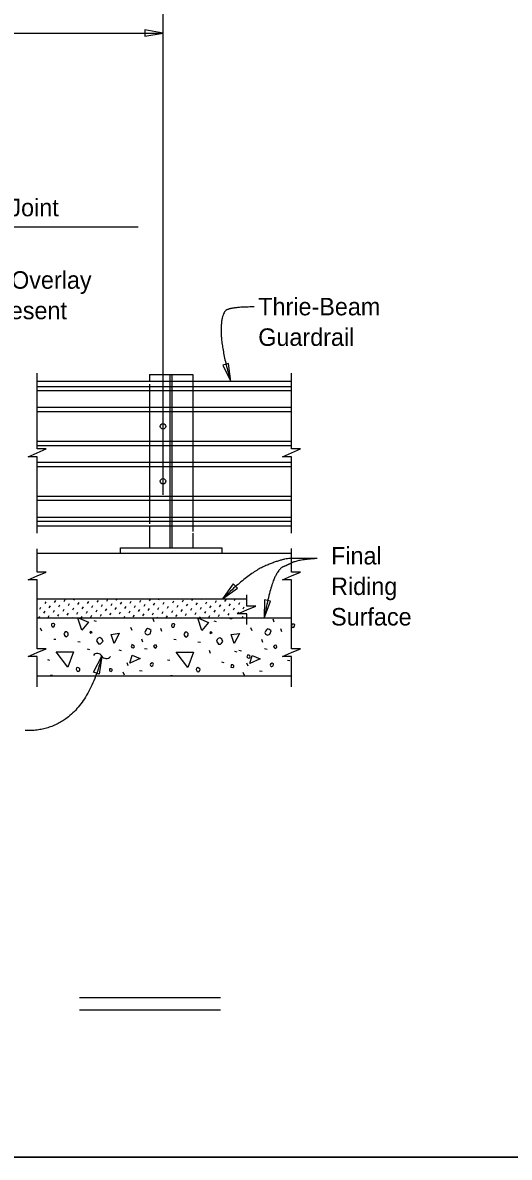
# Model space of a CAD drawing. Extents: x 0 to 41.1, y 0 to 25.9.
# Drawn here: x 15.65 to 21.27, y 0 to 13.09 of the extents above; entities that cross this region are included whole.
import ezdxf

# ---------------------------------------------------------------- set-up
doc = ezdxf.new("R2010")
doc.units = 0
for name, color, linetype in [('Dimension', 7, 'Continuous'), ('ExistSuperStruct', 7, 'Continuous'), ('Miscellaneous', 7, 'Continuous'), ('Miscellaneous1', 7, 'Continuous'), ('SteelMisc', 7, 'Continuous'), ('SteelMisc_h', 7, 'Continuous'), ('TextStructures', 7, 'Continuous')]:
    doc.layers.add(name, color=color, linetype=linetype)

msp = doc.modelspace()

# ---------------------------------------------------------------- linework, layer by layer
at = {"layer": 'Dimension'}
for p, q in [((17.272, 7.641), (17.272, 21.686)), ((16.984, 10.732), (11.432, 10.732)), ((16.308, 1.842), (17.936, 1.842)), ((16.308, 1.7), (17.936, 1.7))]:
    msp.add_line(p, q, dxfattribs=at)
for points in [[(5.085, 12.97), (11.216, 12.97), (11.216, 13.073), (11.261, 12.97), (11.306, 12.866), (11.306, 12.97), (17.272, 12.97)], [(15.819, 7.199), (15.819, 8.082), (15.716, 8.082), (15.819, 8.127), (15.923, 8.172), (15.819, 8.172), (15.819, 9.045)], [(18.755, 7.199), (18.755, 8.082), (18.652, 8.082), (18.755, 8.127), (18.858, 8.172), (18.755, 8.172), (18.755, 9.045)], [(15.819, 6.192), (15.819, 6.662), (15.716, 6.662), (15.819, 6.707), (15.923, 6.752), (15.819, 6.752), (15.819, 7.02)], [(18.755, 6.192), (18.755, 6.662), (18.652, 6.662), (18.755, 6.707), (18.858, 6.752), (18.755, 6.752), (18.755, 7.023)], [(18.241, 6.148), (18.241, 6.269), (18.137, 6.269), (18.241, 6.314), (18.344, 6.359), (18.241, 6.359), (18.241, 6.489)], [(15.819, 5.427), (15.819, 5.777), (15.716, 5.777), (15.819, 5.822), (15.923, 5.867), (15.819, 5.867), (15.819, 6.192)], [(18.755, 5.427), (18.755, 5.777), (18.652, 5.777), (18.755, 5.822), (18.858, 5.867), (18.755, 5.867), (18.755, 6.192)]]:
    msp.add_lwpolyline(points, dxfattribs=at)
for points in [[(17.272, 12.97), (17.064, 13.005), (17.064, 12.934)], [(18.054, 8.948), (18.029, 9.158), (17.961, 9.138)], [(17.96, 6.443), (18.133, 6.565), (18.083, 6.615)], [(18.438, 6.219), (18.512, 6.417), (18.443, 6.43)], [(16.567, 5.783), (16.537, 5.574), (16.47, 5.596)]]:
    msp.add_lwpolyline(points, close=True, dxfattribs=at)
for centre, start, end in [((16.515, 5.753), 30.0081, 141.7354), ((16.618, 5.813), 210.0081, 321.7354)]:
    msp.add_arc(centre, 0.0596, start, end, dxfattribs=at)
for points in [[(18.324, 9.81), (18.084, 9.81), (17.942, 9.746), (17.942, 9.325), (18.054, 8.948)], [(19.049, 6.909), (18.858, 6.909), (18.653, 6.909), (18.257, 6.74), (17.96, 6.443)], [(19.049, 6.909), (18.823, 6.891), (18.699, 6.827), (18.616, 6.797), (18.512, 6.597), (18.438, 6.219)], [(16.567, 5.783), (16.347, 4.909), (15.683, 4.922)]]:
    msp.add_open_spline(points, degree=2, dxfattribs=at)
at = {"layer": 'ExistSuperStruct'}
for p, q in [((15.819, 6.97), (18.755, 6.97)), ((18.241, 6.439), (15.819, 6.439)), ((18.755, 6.22), (15.819, 6.22)), ((15.819, 5.553), (18.755, 5.553))]:
    msp.add_line(p, q, dxfattribs=at)
at = {"layer": 'Miscellaneous'}
for p, q in [((15.862, 6.436), (15.863, 6.439)), ((16.021, 6.4), (16.034, 6.422)), ((16.132, 6.413), (16.145, 6.435)), ((16.243, 6.426), (16.25, 6.439)), ((16.513, 6.403), (16.526, 6.425)), ((16.623, 6.416), (16.636, 6.438)), ((16.734, 6.429), (16.74, 6.439)), ((16.893, 6.393), (16.906, 6.415)), ((17.004, 6.406), (17.017, 6.428)), ((17.115, 6.419), (17.126, 6.439)), ((17.225, 6.432), (17.229, 6.439)), ((17.385, 6.396), (17.398, 6.419)), ((17.495, 6.409), (17.508, 6.431)), ((17.606, 6.422), (17.616, 6.439)), ((17.717, 6.435), (17.719, 6.439)), ((17.876, 6.399), (17.889, 6.422)), ((17.987, 6.412), (18, 6.434)), ((18.097, 6.425), (18.105, 6.439)), ((18.208, 6.438), (18.208, 6.439)), ((15.849, 6.325), (15.862, 6.348)), ((15.898, 6.276), (15.911, 6.299)), ((15.911, 6.387), (15.924, 6.409)), ((15.96, 6.338), (15.973, 6.361)), ((16.008, 6.289), (16.021, 6.312)), ((16.07, 6.351), (16.083, 6.374)), ((16.119, 6.302), (16.132, 6.325)), ((16.181, 6.364), (16.194, 6.387)), ((16.23, 6.315), (16.243, 6.338)), ((16.279, 6.266), (16.291, 6.289)), ((16.291, 6.377), (16.304, 6.4)), ((16.34, 6.328), (16.353, 6.351)), ((16.389, 6.279), (16.402, 6.302)), ((16.402, 6.39), (16.415, 6.412)), ((16.451, 6.341), (16.464, 6.364)), ((16.5, 6.292), (16.513, 6.315)), ((16.562, 6.354), (16.575, 6.377)), ((16.61, 6.305), (16.623, 6.328)), ((16.672, 6.367), (16.685, 6.39)), ((16.721, 6.318), (16.734, 6.341)), ((16.77, 6.27), (16.783, 6.292)), ((16.783, 6.38), (16.796, 6.403)), ((16.832, 6.331), (16.845, 6.354)), ((16.88, 6.282), (16.893, 6.305)), ((16.942, 6.344), (16.955, 6.367)), ((16.991, 6.295), (17.004, 6.318)), ((17.053, 6.357), (17.066, 6.38)), ((17.102, 6.308), (17.115, 6.331)), ((17.164, 6.37), (17.177, 6.393)), ((17.212, 6.321), (17.225, 6.344)), ((17.261, 6.273), (17.274, 6.295)), ((17.274, 6.383), (17.287, 6.406)), ((17.323, 6.334), (17.336, 6.357)), ((17.372, 6.285), (17.385, 6.308)), ((17.434, 6.347), (17.447, 6.37)), ((17.482, 6.298), (17.495, 6.321)), ((17.544, 6.36), (17.557, 6.383)), ((17.593, 6.311), (17.606, 6.334)), ((17.642, 6.263), (17.655, 6.285)), ((17.655, 6.373), (17.668, 6.396)), ((17.704, 6.324), (17.717, 6.347)), ((17.753, 6.276), (17.766, 6.298)), ((17.766, 6.386), (17.779, 6.409)), ((17.814, 6.337), (17.827, 6.36)), ((17.863, 6.289), (17.876, 6.311)), ((17.925, 6.35), (17.938, 6.373)), ((17.974, 6.301), (17.987, 6.324)), ((18.036, 6.363), (18.049, 6.386)), ((18.084, 6.314), (18.097, 6.337)), ((18.133, 6.266), (18.146, 6.288)), ((18.146, 6.376), (18.159, 6.399)), ((18.195, 6.327), (18.208, 6.35)), ((15.839, 6.22), (15.849, 6.237)), ((15.947, 6.228), (15.96, 6.25)), ((16.057, 6.241), (16.07, 6.263)), ((16.168, 6.254), (16.181, 6.276)), ((16.225, 6.22), (16.23, 6.227)), ((16.329, 6.22), (16.34, 6.24)), ((16.438, 6.231), (16.451, 6.253)), ((16.473, 6.193), (16.501, 6.185)), ((16.549, 6.244), (16.562, 6.266)), ((16.659, 6.257), (16.672, 6.279)), ((16.715, 6.22), (16.721, 6.23)), ((16.819, 6.221), (16.832, 6.243)), ((16.929, 6.234), (16.942, 6.256)), ((17.04, 6.247), (17.053, 6.269)), ((17.102, 6.22), (17.102, 6.22)), ((17.151, 6.26), (17.164, 6.282)), ((17.171, 6.177), (17.157, 6.212)), ((17.205, 6.22), (17.212, 6.233)), ((17.31, 6.224), (17.323, 6.246)), ((17.421, 6.237), (17.434, 6.259)), ((17.531, 6.25), (17.544, 6.272)), ((17.591, 6.22), (17.593, 6.223)), ((17.694, 6.22), (17.704, 6.236)), ((17.801, 6.227), (17.814, 6.249)), ((17.858, 6.189), (17.886, 6.182)), ((17.912, 6.24), (17.925, 6.262)), ((18.023, 6.253), (18.036, 6.275)), ((18.081, 6.22), (18.084, 6.226)), ((18.184, 6.22), (18.195, 6.239)), ((18.556, 6.173), (18.542, 6.208)), ((15.874, 6.068), (15.86, 6.103)), ((16.915, 6.076), (16.901, 6.111)), ((17.259, 6.064), (17.245, 6.099)), ((18.3, 6.072), (18.285, 6.108)), ((18.644, 6.061), (18.63, 6.096)), ((16.012, 5.979), (16.037, 5.976)), ((16.288, 5.951), (16.318, 5.946)), ((17.04, 5.943), (17.028, 5.977)), ((17.397, 5.976), (17.422, 5.972)), ((17.673, 5.947), (17.703, 5.942)), ((18.425, 5.94), (18.413, 5.973)), ((16.395, 5.867), (16.423, 5.86)), ((16.763, 5.853), (16.791, 5.846)), ((17.059, 5.871), (17.089, 5.866)), ((17.821, 5.813), (17.809, 5.847)), ((18.095, 5.84), (18.123, 5.833)), ((18.148, 5.85), (18.176, 5.843)), ((18.444, 5.868), (18.474, 5.863)), ((15.938, 5.742), (15.964, 5.737)), ((16.869, 5.671), (16.857, 5.704)), ((17.323, 5.739), (17.349, 5.734)), ((17.948, 5.714), (17.975, 5.709)), ((18.254, 5.667), (18.241, 5.701)), ((18.707, 5.735), (18.734, 5.73)), ((16.827, 5.561), (16.812, 5.596)), ((16.999, 5.617), (17.031, 5.613)), ((18.211, 5.557), (18.197, 5.593)), ((18.384, 5.613), (18.416, 5.61))]:
    msp.add_line(p, q, dxfattribs=at)
for points in [[(15.984, 6.135), (15.993, 6.119), (16.012, 6.121), (16.021, 6.133), (16.023, 6.152), (16.01, 6.158), (16.002, 6.16), (15.991, 6.156), (15.987, 6.152), (15.984, 6.135)], [(16.336, 6.08), (16.29, 6.22)], [(16.304, 6.22), (16.413, 6.172), (16.336, 6.08)], [(17.369, 6.131), (17.377, 6.115), (17.397, 6.117), (17.406, 6.13), (17.407, 6.149), (17.395, 6.154), (17.386, 6.156), (17.376, 6.152), (17.372, 6.149), (17.369, 6.131)], [(17.72, 6.076), (17.674, 6.22)], [(17.681, 6.22), (17.798, 6.168), (17.72, 6.076)], [(18.042, 6.22), (18.045, 6.214), (18.041, 6.217)], [(18.045, 6.214), (18.066, 6.214), (18.072, 6.22)], [(18.753, 6.128), (18.762, 6.112), (18.782, 6.114), (18.79, 6.126), (18.792, 6.145), (18.78, 6.151), (18.771, 6.152), (18.76, 6.149), (18.757, 6.145), (18.753, 6.128)], [(16.129, 6.036), (16.139, 6.015), (16.157, 6.004), (16.171, 6.015), (16.178, 6.025), (16.178, 6.046), (16.162, 6.062), (16.143, 6.061), (16.134, 6.052), (16.129, 6.036)], [(16.435, 6.045), (16.454, 6.054), (16.447, 6.061), (16.435, 6.066), (16.429, 6.054), (16.435, 6.045)], [(16.708, 5.929), (16.674, 6.033), (16.768, 6.046), (16.708, 5.929)], [(17.069, 6.039), (17.092, 6.026), (17.122, 6.039), (17.134, 6.076), (17.116, 6.094), (17.093, 6.099), (17.083, 6.092), (17.07, 6.072), (17.062, 6.056), (17.069, 6.039)], [(17.514, 6.032), (17.524, 6.011), (17.542, 6), (17.556, 6.011), (17.563, 6.022), (17.563, 6.043), (17.547, 6.059), (17.528, 6.057), (17.519, 6.048), (17.514, 6.032)], [(17.819, 6.041), (17.839, 6.05), (17.832, 6.057), (17.819, 6.062), (17.814, 6.05), (17.819, 6.041)], [(18.093, 5.926), (18.059, 6.03), (18.153, 6.042), (18.093, 5.926)], [(18.453, 6.035), (18.476, 6.023), (18.506, 6.035), (18.519, 6.072), (18.501, 6.09), (18.478, 6.095), (18.468, 6.088), (18.455, 6.069), (18.446, 6.053), (18.453, 6.035)], [(16.505, 5.96), (16.528, 5.923), (16.551, 5.924), (16.56, 5.933), (16.58, 5.953), (16.567, 5.983), (16.543, 5.997), (16.525, 5.99), (16.511, 5.976), (16.505, 5.96)], [(16.914, 5.88), (16.926, 5.878), (16.939, 5.884), (16.942, 5.894), (16.937, 5.903), (16.926, 5.91), (16.914, 5.916), (16.907, 5.901), (16.903, 5.891), (16.914, 5.88)], [(17.171, 5.884), (17.181, 5.873), (17.192, 5.88), (17.199, 5.891), (17.195, 5.909), (17.187, 5.91), (17.174, 5.909), (17.164, 5.898), (17.171, 5.884)], [(17.89, 5.956), (17.913, 5.919), (17.936, 5.921), (17.945, 5.93), (17.964, 5.949), (17.952, 5.979), (17.927, 5.993), (17.91, 5.986), (17.895, 5.972), (17.89, 5.956)], [(18.555, 5.88), (18.566, 5.87), (18.577, 5.877), (18.584, 5.887), (18.58, 5.905), (18.571, 5.907), (18.559, 5.905), (18.548, 5.894), (18.555, 5.88)], [(16.173, 5.656), (16.039, 5.833), (16.238, 5.831), (16.173, 5.656)], [(16.888, 5.7), (16.916, 5.792), (17.01, 5.755), (16.888, 5.7)], [(17.558, 5.652), (17.423, 5.829), (17.623, 5.827), (17.558, 5.652)], [(18.25, 5.761), (18.262, 5.759), (18.275, 5.765), (18.278, 5.775), (18.273, 5.784), (18.262, 5.791), (18.25, 5.797), (18.243, 5.782), (18.239, 5.772), (18.25, 5.761)], [(18.272, 5.696), (18.301, 5.788), (18.394, 5.751), (18.272, 5.696)], [(16.272, 5.624), (16.281, 5.608), (16.302, 5.604), (16.311, 5.62), (16.314, 5.635), (16.306, 5.643), (16.29, 5.652), (16.274, 5.647), (16.269, 5.631), (16.272, 5.624)], [(16.653, 5.611), (16.672, 5.606), (16.685, 5.614), (16.687, 5.627), (16.683, 5.63), (16.669, 5.637), (16.656, 5.636), (16.655, 5.623), (16.653, 5.611)], [(17.135, 5.665), (17.142, 5.665), (17.156, 5.672), (17.162, 5.688), (17.16, 5.696), (17.146, 5.703), (17.128, 5.693), (17.125, 5.682), (17.128, 5.672), (17.135, 5.665)], [(17.657, 5.62), (17.666, 5.604), (17.687, 5.601), (17.696, 5.617), (17.699, 5.631), (17.69, 5.64), (17.674, 5.649), (17.659, 5.643), (17.653, 5.627), (17.657, 5.62)], [(18.056, 5.656), (18.076, 5.65), (18.088, 5.659), (18.09, 5.672), (18.086, 5.675), (18.072, 5.682), (18.06, 5.681), (18.058, 5.668), (18.056, 5.656)], [(18.52, 5.661), (18.527, 5.661), (18.541, 5.668), (18.546, 5.684), (18.545, 5.693), (18.531, 5.7), (18.513, 5.689), (18.509, 5.679), (18.513, 5.668), (18.52, 5.661)], [(15.997, 5.553), (15.996, 5.557), (15.973, 5.559), (15.971, 5.553)], [(17.381, 5.553), (17.381, 5.553), (17.358, 5.555), (17.357, 5.553)]]:
    msp.add_lwpolyline(points, dxfattribs=at)
at = {"layer": 'Miscellaneous1'}
msp.add_lwpolyline([(0, 25.946), (41.051, 25.946), (41.051, 0), (0, 0)], close=True, dxfattribs=at)
at = {"layer": 'SteelMisc'}
for p, q in [((17.116, 9.032), (17.616, 9.032)), ((17.116, 9.032), (17.116, 8.949)), ((18.755, 8.949), (15.819, 8.949)), ((15.819, 8.893), (18.755, 8.893)), ((15.819, 8.845), (18.755, 8.845)), ((15.819, 8.652), (18.755, 8.652)), ((15.819, 8.604), (18.755, 8.604)), ((15.819, 8.26), (18.755, 8.26)), ((15.819, 8.212), (18.755, 8.212)), ((15.819, 8.019), (18.755, 8.019)), ((15.819, 7.971), (18.755, 7.971)), ((15.819, 7.627), (18.755, 7.627)), ((15.819, 7.579), (18.755, 7.579)), ((15.819, 7.386), (18.755, 7.386)), ((15.819, 7.338), (18.755, 7.338)), ((18.755, 7.282), (15.819, 7.282)), ((17.116, 7.282), (17.116, 7.032)), ((17.616, 7.199), (17.616, 7.032)), ((16.782, 7.032), (17.949, 7.032)), ((16.782, 6.97), (16.782, 7.032)), ((16.782, 6.97), (17.949, 6.97)), ((17.116, 7.032), (17.616, 7.032)), ((17.949, 7.032), (17.949, 6.97))]:
    msp.add_line(p, q, dxfattribs=at)
for centre in [(17.272, 8.432), (17.272, 7.799)]:
    msp.add_circle(centre, 0.0312, dxfattribs=at)
at = {"layer": 'SteelMisc_h'}
for p, q in [((17.355, 7.032), (17.355, 9.032)), ((17.376, 7.032), (17.376, 9.032)), ((17.616, 9.032), (17.616, 7.219)), ((17.116, 8.92), (17.116, 7.308))]:
    msp.add_line(p, q, dxfattribs=at)
at = {"layer": 'TextStructures'}
msp.add_lwpolyline([(0, 0), (41.051, 0), (41.051, 25.946), (0, 25.946)], close=True, dxfattribs=at)

# ---------------------------------------------------------------- texts
at = {"layer": 'Dimension'}
for s, p in [('Asphalt Overlay', (14.545, 10.02)), ('when present', (14.545, 9.668)), ('Thrie-Beam ', (18.371, 9.713)), ('Guardrail', (18.371, 9.361)), ('Final ', (19.211, 6.839)), ('Riding ', (19.211, 6.487)), ('Surface', (19.211, 6.135))]:
    msp.add_text(s, height=0.2016, dxfattribs=at).set_placement(p)
at = {"layer": 'TextStructures'}
msp.add_text('Intermediate Deck Joint', height=0.2016, dxfattribs=at).set_placement((13.237, 10.856))

doc.saveas('drawing.dxf')
